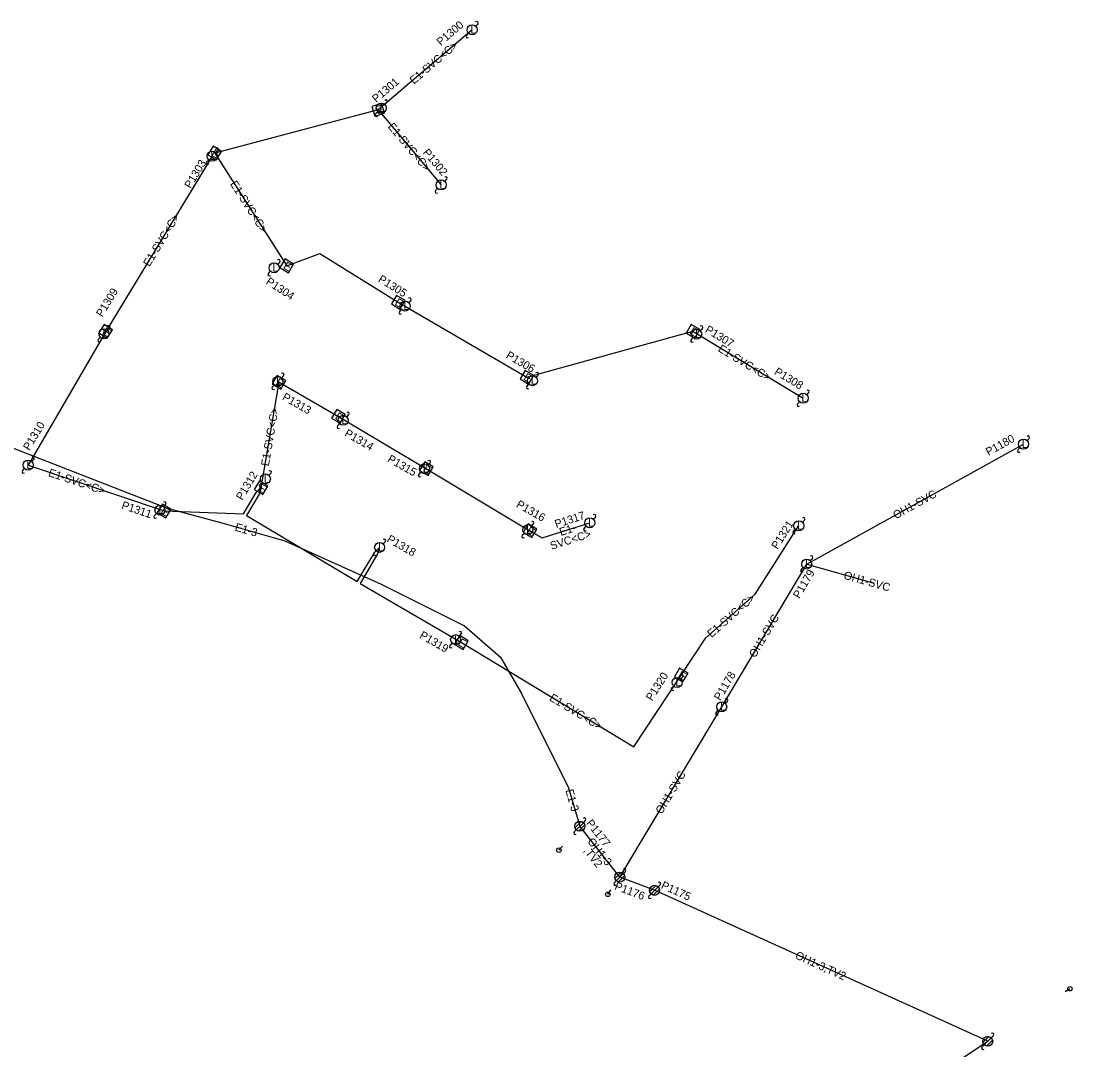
# Model space of a CAD drawing. Extents: x 2336688 to 2352634, y 362473 to 369571.
# Drawn here: x 2346202 to 2346727, y 369052 to 369566 of the extents above; entities that cross this region are included whole.
import ezdxf

# ---------------------------------------------------------------- set-up
doc = ezdxf.new("R2010")
doc.units = 0
for name, color, linetype in [('RD_EX_DV_Prop', 7, 'Continuous'), ('RD_EX_DV_TX_Prop', 7, 'Continuous'), ('RD_HC_Data_Tic', 7, 'Continuous'), ('RD_PD_Final_TrvlWay', 7, 'Continuous'), ('RD_PD_PatLn4', 7, 'Continuous'), ('RD_SHT_ShtClip', 7, 'Continuous')]:
    doc.layers.add(name, color=color, linetype=linetype)

# ---------------------------------------------------------------- blocks, each defined once
blk = doc.blocks.new('GW')
at = {"layer": 'RD_HC_Data_Tic'}
blk.add_line((0, 0), (0, 5), dxfattribs=at)
blk.add_circle((0, 0), 2, dxfattribs=at)

msp = doc.modelspace()

# ---------------------------------------------------------------- linework, layer by layer
at = {"layer": 'RD_HC_Data_Tic'}
for p, q in [((2346428.8, 369563.24), (2346429.86, 369564.3)), ((2346424.21, 369558.65), (2346425.27, 369559.71)), ((2346383.36, 369524.08), (2346384.42, 369525.14)), ((2346378.77, 369519.48), (2346379.83, 369520.54)), ((2346298.88, 369500.07), (2346299.94, 369501.13)), ((2346294.29, 369495.47), (2346295.35, 369496.53)), ((2346408.73, 369481.1), (2346409.8, 369482.16)), ((2346413.33, 369485.69), (2346414.39, 369486.75)), ((2346329.8, 369444.29), (2346330.86, 369445.35)), ((2346325.21, 369439.7), (2346326.27, 369440.76)), ((2346395.31, 369425.15), (2346396.37, 369426.21)), ((2346390.71, 369420.56), (2346391.77, 369421.62)), ((2346244.73, 369411.3), (2346245.79, 369412.37)), ((2346541.1, 369411.15), (2346542.16, 369412.21)), ((2346240.14, 369406.71), (2346241.2, 369407.77)), ((2346536.5, 369406.56), (2346537.56, 369407.62)), ((2346331.71, 369387.52), (2346332.77, 369388.58)), ((2346458.97, 369387.85), (2346460.03, 369388.91)), ((2346327.11, 369382.92), (2346328.17, 369383.98)), ((2346454.37, 369383.25), (2346455.44, 369384.31)), ((2346594.32, 369379.09), (2346595.38, 369380.15)), ((2346589.72, 369374.49), (2346590.78, 369375.55)), ((2346364.34, 369368.07), (2346365.4, 369369.13)), ((2346359.74, 369363.47), (2346360.8, 369364.53)), ((2346704.48, 369356.14), (2346705.54, 369357.2)), ((2346699.88, 369351.54), (2346700.95, 369352.6)), ((2346206.85, 369345.67), (2346207.91, 369346.73)), ((2346202.26, 369341.08), (2346203.32, 369342.14)), ((2346400.36, 369339.27), (2346401.42, 369340.33)), ((2346404.96, 369343.87), (2346406.02, 369344.93)), ((2346320.84, 369334.17), (2346321.9, 369335.23)), ((2346325.44, 369338.77), (2346326.5, 369339.83)), ((2346268.15, 369318.59), (2346269.21, 369319.65)), ((2346272.75, 369323.19), (2346273.81, 369324.25)), ((2346456.69, 369313.42), (2346457.75, 369314.48)), ((2346487.63, 369316.85), (2346488.69, 369317.91)), ((2346592.16, 369315.37), (2346593.22, 369316.43)), ((2346452.09, 369308.82), (2346453.15, 369309.88)), ((2346483.03, 369312.25), (2346484.1, 369313.31)), ((2346587.56, 369310.77), (2346588.62, 369311.83)), ((2346382.56, 369304.56), (2346383.62, 369305.62)), ((2346377.96, 369299.97), (2346379.02, 369301.03)), ((2346596.09, 369296.22), (2346597.15, 369297.28)), ((2346591.5, 369291.62), (2346592.56, 369292.68)), ((2346420.56, 369258.43), (2346421.62, 369259.5)), ((2346415.96, 369253.84), (2346417.02, 369254.9)), ((2346531.35, 369237.06), (2346532.41, 369238.12)), ((2346526.76, 369232.47), (2346527.82, 369233.53)), ((2346553.6, 369224.88), (2346554.66, 369225.94)), ((2346549, 369220.29), (2346550.06, 369221.35)), ((2346478.08, 369160.6), (2346479.14, 369161.66)), ((2346478.49, 369162.78), (2346481.55, 369165.85)), ((2346479.14, 369161.66), (2346482.67, 369165.2)), ((2346480.26, 369161.02), (2346483.32, 369164.08)), ((2346482.67, 369165.2), (2346483.73, 369166.26)), ((2346498.47, 369137.34), (2346501.53, 369140.4)), ((2346502.65, 369139.76), (2346503.71, 369140.82)), ((2346498.05, 369135.16), (2346499.11, 369136.22)), ((2346499.11, 369136.22), (2346502.65, 369139.76)), ((2346500.23, 369135.57), (2346503.29, 369138.64)), ((2346515.85, 369130.75), (2346518.92, 369133.81)), ((2346516.5, 369129.63), (2346520.04, 369133.16)), ((2346517.62, 369128.98), (2346520.68, 369132.04)), ((2346520.04, 369133.16), (2346521.1, 369134.22)), ((2346515.44, 369128.57), (2346516.5, 369129.63)), ((2346682.39, 369055.29), (2346685.45, 369058.35)), ((2346683.04, 369054.17), (2346686.57, 369057.7)), ((2346684.16, 369053.52), (2346687.22, 369056.58)), ((2346686.57, 369057.7), (2346687.64, 369058.76)), ((2346681.98, 369053.11), (2346683.04, 369054.17))]:
    msp.add_line(p, q, dxfattribs=at)
for centre in [(2346427.03, 369561.48), (2346381.59, 369522.31), (2346297.11, 369498.3), (2346411.56, 369483.93), (2346328.03, 369442.53), (2346393.54, 369423.39), (2346242.97, 369409.54), (2346539.33, 369409.38), (2346329.94, 369385.75), (2346457.2, 369386.08), (2346592.55, 369377.32), (2346362.57, 369366.3), (2346702.71, 369354.37), (2346205.09, 369343.91), (2346403.19, 369342.1), (2346323.67, 369337), (2346270.98, 369321.42), (2346454.92, 369311.65), (2346485.86, 369315.08), (2346590.39, 369313.6), (2346380.79, 369302.8), (2346594.32, 369294.45), (2346418.79, 369256.67), (2346529.58, 369235.29), (2346551.83, 369223.11), (2346480.9, 369163.43), (2346500.88, 369137.99), (2346518.27, 369131.39), (2346684.81, 369055.93)]:
    msp.add_circle(centre, 2.5, dxfattribs=at)
for centre, start, end in [((2346429.33, 369564.83), 315, 135), ((2346424.74, 369558.12), 135, 315), ((2346383.89, 369525.67), 315, 135), ((2346379.3, 369518.95), 135, 315), ((2346299.41, 369501.66), 315, 135), ((2346294.82, 369494.94), 135, 315), ((2346413.86, 369487.28), 315, 135), ((2346409.26, 369480.57), 135, 315), ((2346330.33, 369445.88), 315, 135), ((2346325.74, 369439.17), 135, 315), ((2346395.84, 369426.74), 315, 135), ((2346391.24, 369420.03), 135, 315), ((2346245.26, 369412.9), 315, 135), ((2346541.63, 369412.74), 315, 135), ((2346240.67, 369406.18), 135, 315), ((2346537.03, 369406.03), 135, 315), ((2346332.24, 369389.11), 315, 135), ((2346459.5, 369389.44), 315, 135), ((2346327.64, 369382.39), 135, 315), ((2346454.9, 369382.72), 135, 315), ((2346594.85, 369380.68), 315, 135), ((2346590.25, 369373.96), 135, 315), ((2346364.87, 369369.66), 315, 135), ((2346360.27, 369362.94), 135, 315), ((2346705.01, 369357.73), 315, 135), ((2346700.41, 369351.01), 135, 315), ((2346207.38, 369347.26), 315, 135), ((2346405.49, 369345.46), 315, 135), ((2346202.79, 369340.55), 135, 315), ((2346325.97, 369340.36), 315, 135), ((2346400.89, 369338.74), 135, 315), ((2346321.37, 369333.64), 135, 315), ((2346273.28, 369324.78), 315, 135), ((2346488.16, 369318.44), 315, 135), ((2346268.68, 369318.06), 135, 315), ((2346457.22, 369315.01), 315, 135), ((2346592.69, 369316.96), 315, 135), ((2346452.62, 369308.29), 135, 315), ((2346483.56, 369311.72), 135, 315), ((2346588.09, 369310.24), 135, 315), ((2346383.09, 369306.15), 315, 135), ((2346378.49, 369299.44), 135, 315), ((2346596.62, 369297.81), 315, 135), ((2346592.03, 369291.09), 135, 315), ((2346421.09, 369260.03), 315, 135), ((2346416.49, 369253.31), 135, 315), ((2346531.88, 369238.65), 315, 135), ((2346527.29, 369231.94), 135, 315), ((2346554.13, 369226.47), 315, 135), ((2346549.53, 369219.76), 135, 315), ((2346483.2, 369166.79), 315, 135), ((2346478.61, 369160.07), 135, 315), ((2346503.18, 369141.35), 315, 135), ((2346498.58, 369134.63), 135, 315), ((2346520.57, 369134.75), 315, 135), ((2346515.97, 369128.04), 135, 315), ((2346687.11, 369059.29), 315, 135), ((2346682.51, 369052.58), 135, 315)]:
    msp.add_arc(centre, 0.75, start, end, dxfattribs=at)
at = {"layer": 'RD_PD_Final_TrvlWay'}
msp.add_line((2346380.07, 369521.46), (2346411.56, 369483.93), dxfattribs=at)
for points in [[(2346427.03, 369561.48), (2346380.07, 369521.46), (2346298.4, 369499.83), (2346334.37, 369443.5), (2346350.98, 369449.64), (2346390.09, 369425.28), (2346454.43, 369387.82), (2346537.46, 369410.77), (2346592.55, 369377.32)], [(2346297.11, 369498.3), (2346243.86, 369410.74), (2346205.09, 369343.91), (2346273.06, 369321.02), (2346312.78, 369319.54), (2346319.12, 369330.17), (2346321.55, 369332.59), (2346320.57, 369329.31), (2346314.23, 369318.68), (2346369.59, 369285.66), (2346378.37, 369300.37), (2346380.79, 369302.8), (2346379.81, 369299.51), (2346371.03, 369284.8), (2346421.71, 369255.25), (2346507.92, 369203.14), (2346531.59, 369238.99), (2346543.86, 369257.57), (2346568.61, 369279.35), (2346590.43, 369313.67)], [(2346139.08, 369414.79), (2346136.9, 369411.65), (2346133.29, 369392.66), (2346191.28, 369354.88), (2346274.59, 369322.42), (2346301.94, 369315.02), (2346333.43, 369305.99), (2346381.65, 369284.4), (2346423.24, 369263.62), (2346441.28, 369247.94), (2346451.74, 369229.69), (2346475.27, 369182.69), (2346480.9, 369163.43)], [(2346321.55, 369332.59), (2346330.5, 369385.28), (2346360.23, 369368.26), (2346404.23, 369342.09), (2346455.95, 369311.09), (2346461.99, 369307.48), (2346485.86, 369315.08)]]:
    msp.add_lwpolyline(points, dxfattribs=at)
for points in [[(2346381.74, 369524.57), (2346376.95, 369523.14), (2346378.39, 369518.35), (2346383.18, 369519.78)], [(2346301.82, 369500.7), (2346297.53, 369503.26), (2346294.97, 369498.97), (2346299.26, 369496.41)], [(2346337.79, 369444.36), (2346333.5, 369446.92), (2346330.94, 369442.63), (2346335.23, 369440.07)], [(2346393.51, 369426.15), (2346389.22, 369428.71), (2346386.66, 369424.42), (2346390.95, 369421.86)], [(2346247.31, 369411.54), (2346243.07, 369414.19), (2346240.41, 369409.95), (2346244.65, 369407.3)], [(2346540.88, 369411.64), (2346536.58, 369414.19), (2346534.03, 369409.89), (2346538.33, 369407.34)], [(2346333.93, 369386.14), (2346329.64, 369388.71), (2346327.07, 369384.42), (2346331.36, 369381.85)], [(2346457.86, 369388.68), (2346453.57, 369391.25), (2346451, 369386.96), (2346455.29, 369384.39)], [(2346363.65, 369369.12), (2346359.36, 369371.69), (2346356.8, 369367.4), (2346361.09, 369364.83)], [(2346407.65, 369342.96), (2346403.35, 369345.51), (2346400.8, 369341.22), (2346405.1, 369338.66)], [(2346324.97, 369333.45), (2346320.68, 369336.02), (2346318.12, 369331.73), (2346322.41, 369329.16)], [(2346276.5, 369321.81), (2346272.26, 369324.46), (2346269.61, 369320.23), (2346273.85, 369317.57)], [(2346459.37, 369311.97), (2346455.08, 369314.52), (2346452.52, 369310.22), (2346456.82, 369307.67)], [(2346425.14, 369256.13), (2346420.84, 369258.68), (2346418.29, 369254.38), (2346422.58, 369251.83)], [(2346535.02, 369239.87), (2346530.72, 369242.42), (2346528.17, 369238.12), (2346532.47, 369235.57)]]:
    msp.add_lwpolyline(points, close=True, dxfattribs=at)
at = {"layer": 'RD_SHT_ShtClip'}
for p, q in [((2346594.32, 369294.45), (2346702.71, 369354.37)), ((2346551.83, 369223.11), (2346594.32, 369294.45)), ((2346594.32, 369294.45), (2346628, 369284.86)), ((2346500.88, 369137.99), (2346551.83, 369223.11)), ((2346500.88, 369137.99), (2346480.9, 369163.43)), ((2346518.27, 369131.39), (2346500.88, 369137.99)), ((2346684.81, 369055.93), (2346518.27, 369131.39)), ((2346611.77, 369007.96), (2346684.81, 369055.93))]:
    msp.add_line(p, q, dxfattribs=at)

# ---------------------------------------------------------------- block references
at = {"layer": 'RD_HC_Data_Tic'}
for p, xscale, yscale, rotation in [((2346470.4, 369151.44), 0.5546771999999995, 0.5546771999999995, -41.25424185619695), ((2346494.89, 369129.38), 0.5546771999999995, 0.5546771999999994, -34.81893675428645), ((2346725.9, 369082.19), 0.5546771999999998, 0.5546771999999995, 122.54018367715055)]:
    msp.add_blockref('GW', p, dxfattribs=dict(at, xscale=xscale, yscale=yscale, rotation=rotation))

# ---------------------------------------------------------------- texts
at = {"layer": 'RD_EX_DV_Prop'}
for s, rotation, p in [('E1-SVC<C>', 40.4313, (2346397.86, 369533.99)), ('E1-SVC<C>', 310.0044, (2346384.63, 369512.91)), ('E1-SVC<C>', 302.5581, (2346305.84, 369484.45)), ('E1-SVC<C>', 58.6903, (2346265.7, 369442.79)), ('E1-SVC<C>', 328.7388, (2346549.67, 369401.01)), ('E1-SVC<C>', 80.3553, (2346325.38, 369343.19)), ('E1-SVC<C>', 341.3905, (2346214.84, 369338.51)), ('E1-3', 343.9957, (2346308.14, 369311.2)), ('E1-', 17.663, (2346471.4, 369308.45)), ('SVC<C>', 17.663, (2346466.77, 369301.51)), ('E1-SVC<C>', 41.3459, (2346546.75, 369257.45)), ('E1-SVC<C>', 328.8487, (2346465.32, 369226.56)), ('E1-3', 286.3082, (2346473.63, 369181.3))]:
    msp.add_text(s, height=4, rotation=rotation, dxfattribs=at).set_placement(p)
at = {"layer": 'RD_EX_DV_TX_Prop'}
for s, rotation, p in [('P1300', 40.4313, (2346411.39, 369553.24)), ('P1301', 40.4313, (2346379.14, 369524.81)), ('P1302', 310.0044, (2346402.16, 369499.96)), ('P1303', 58.6903, (2346286.29, 369481.78)), ('P1304', 326.4598, (2346323.58, 369434.71)), ('P1305', 328.0857, (2346379.71, 369435.82)), ('P1309', 58.6903, (2346242.16, 369417.6)), ('P1307', 328.7388, (2346543.17, 369410.57)), ('P1306', 329.7914, (2346443.63, 369397.67)), ('P1308', 328.7388, (2346577.77, 369389.53)), ('P1313', 330.2062, (2346331.75, 369376.82)), ('P1310', 58.6903, (2346205.67, 369350.86)), ('P1314', 330.2062, (2346362.9, 369358.67)), ('P1180', 28.9353, (2346685.19, 369348.45)), ('P1315', 330.2062, (2346384.39, 369345.83)), ('P1312', 59.1846, (2346312.13, 369325.98)), ('P1311', 341.3905, (2346251.42, 369322.25)), ('P1316', 330.2062, (2346448.76, 369323.18)), ('P1317', 17.663, (2346469.07, 369312.43)), ('P1321', 57.73, (2346579.74, 369301.49)), ('P1318', 329.8797, (2346384.06, 369305.85)), ('P1179', 59.2173, (2346590.62, 369276.87)), ('P1319', 329.8797, (2346400.4, 369257.76)), ('P1320', 57.3038, (2346516.98, 369225.72)), ('P1178', 59.2173, (2346551.1, 369225.91)), ('P1177', 308.1364, (2346483.81, 369164.85)), ('P1176', 339.229, (2346497.97, 369131.96)), ('P1175', 335.6244, (2346521.18, 369132.53))]:
    msp.add_text(s, height=4, rotation=rotation, dxfattribs=at).set_placement(p)
at = {"layer": 'RD_HC_Data_Tic'}
for p in [(2346426.22, 369559.54), (2346380.78, 369520.37), (2346296.3, 369496.36), (2346410.75, 369481.99), (2346327.22, 369440.59), (2346392.73, 369421.45), (2346242.15, 369407.6), (2346538.52, 369407.45), (2346329.13, 369383.81), (2346456.39, 369384.15), (2346591.74, 369375.39), (2346361.76, 369364.37), (2346701.9, 369352.44), (2346204.28, 369341.97), (2346402.38, 369340.17), (2346322.86, 369335.07), (2346270.17, 369319.49), (2346485.05, 369313.15), (2346589.58, 369311.67), (2346454.11, 369309.71), (2346379.98, 369300.86), (2346593.51, 369292.52), (2346417.98, 369254.73), (2346528.77, 369233.36), (2346551.02, 369221.18)]:
    msp.add_text('L', height=4, rotation=360, dxfattribs=at).set_placement(p)
at = {"layer": 'RD_PD_Final_TrvlWay'}
for rotation, p in [(16.6386, (2346379.48, 369519.19)), (329.1356, (2346296.33, 369498.74)), (329.1356, (2346332.3, 369442.4)), (329.1356, (2346388.02, 369424.19)), (327.9549, (2346241.77, 369409.69)), (329.2845, (2346535.39, 369409.66)), (329.1356, (2346452.36, 369386.73)), (329.1356, (2346328.43, 369384.18)), (329.1356, (2346358.16, 369367.16)), (329.2845, (2346402.16, 369340.99)), (329.1356, (2346319.48, 369331.5)), (327.9549, (2346270.97, 369319.97)), (329.2845, (2346453.88, 369309.99)), (329.2845, (2346419.65, 369254.15)), (329.2845, (2346529.53, 369237.89))]:
    msp.add_text('E', height=4, rotation=rotation, dxfattribs=at).set_placement(p)
at = {"layer": 'RD_PD_PatLn4'}
for s, rotation, p in [('OH1-SVC', 28.9353, (2346638.87, 369316.79)), ('OH1-SVC', 344.1027, (2346612.52, 369287.19)), ('OH1-SVC', 59.2173, (2346568.59, 369247.34)), ('OH1-SVC', 59.0989, (2346521.84, 369169.12)), ('OH1-3', 308.1364, (2346484.43, 369155.71)), (',TV2', 308.1364, (2346482.49, 369151.2)), ('OH1-3,TV2', 335.6244, (2346588.2, 369097.51))]:
    msp.add_text(s, height=4, rotation=rotation, dxfattribs=at).set_placement(p)

doc.saveas('drawing.dxf')
